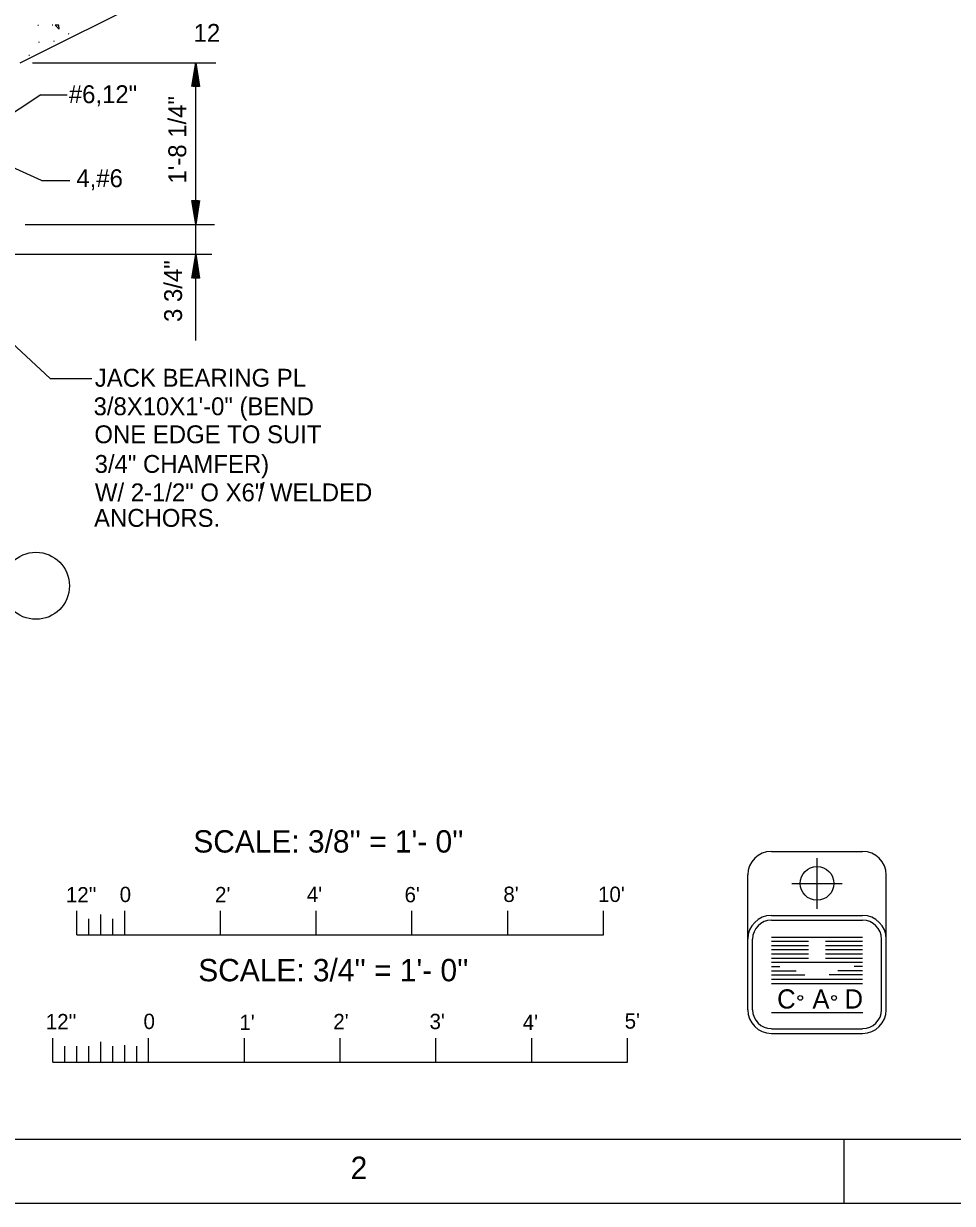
# Model space of a CAD drawing. Extents: x -48 to 108, y -5 to 100.
# Drawn here: x 69.16 to 88.56, y 1.29 to 25.94 of the extents above; entities that cross this region are included whole.
import ezdxf

# ---------------------------------------------------------------- set-up
doc = ezdxf.new("R2010")
doc.units = 0
for name, color, linetype in [('Level 1', 7, 'Continuous'), ('Level 2', 7, 'Continuous'), ('Level 25', 7, 'Continuous'), ('Level 3', 7, 'Continuous'), ('Level 44', 7, 'Continuous'), ('Level 50', 7, 'Continuous')]:
    doc.layers.add(name, color=color, linetype=linetype)

msp = doc.modelspace()

# ---------------------------------------------------------------- linework, layer by layer
at = {"layer": 'Level 1'}
for p, q in [((84.781, 8.644), (86.686, 8.644)), ((85.733, 8.504), (85.733, 7.448)), ((84.288, 5.335), (84.288, 8.152)), ((87.179, 5.335), (87.179, 8.152)), ((85.205, 7.976), (86.261, 7.976)), ((70.275, 6.9), (70.275, 7.4)), ((71.275, 6.9), (71.275, 7.4)), ((73.275, 6.9), (73.275, 7.4)), ((75.275, 6.9), (75.275, 7.4)), ((77.275, 6.9), (77.275, 7.4)), ((79.275, 6.9), (79.275, 7.4)), ((81.275, 6.9), (81.275, 7.4)), ((70.525, 6.9), (70.525, 7.234)), ((70.775, 6.9), (70.775, 7.324)), ((71.025, 6.9), (71.025, 7.234)), ((84.781, 7.307), (86.686, 7.307)), ((84.781, 7.208), (86.686, 7.208)), ((70.275, 6.9), (81.275, 6.9)), ((75.775, 6.9), (75.775, 6.9)), ((84.386, 5.335), (84.386, 6.814)), ((84.781, 6.856), (86.686, 6.856)), ((84.781, 6.768), (85.557, 6.768)), ((84.781, 6.68), (85.557, 6.68)), ((85.909, 6.768), (86.686, 6.768)), ((85.909, 6.68), (86.686, 6.68)), ((87.081, 5.335), (87.081, 6.814)), ((84.781, 6.592), (85.557, 6.592)), ((84.781, 6.504), (85.557, 6.504)), ((84.781, 6.416), (85.557, 6.416)), ((85.909, 6.592), (86.686, 6.592)), ((85.909, 6.504), (86.686, 6.504)), ((85.909, 6.416), (86.686, 6.416)), ((84.781, 6.328), (86.686, 6.328)), ((84.781, 6.24), (84.957, 6.24)), ((86.686, 6.24), (86.51, 6.24)), ((84.781, 6.152), (85.3, 6.152)), ((84.781, 6.064), (85.48, 6.064)), ((84.781, 5.976), (86.686, 5.976)), ((86.686, 6.064), (85.986, 6.064)), ((86.686, 6.152), (86.167, 6.152)), ((84.781, 5.888), (86.686, 5.888)), ((84.781, 5.277), (86.69, 5.277)), ((84.781, 4.941), (86.686, 4.941)), ((69.775, 4.243), (69.775, 4.743)), ((71.775, 4.243), (71.775, 4.743)), ((73.775, 4.243), (73.775, 4.743)), ((75.775, 4.243), (75.775, 4.743)), ((77.775, 4.243), (77.775, 4.743)), ((79.775, 4.243), (79.775, 4.743)), ((81.775, 4.243), (81.775, 4.743)), ((84.781, 4.843), (86.686, 4.843)), ((70.025, 4.243), (70.025, 4.576)), ((70.275, 4.243), (70.275, 4.576)), ((70.525, 4.243), (70.525, 4.576)), ((70.775, 4.243), (70.775, 4.665)), ((71.025, 4.243), (71.025, 4.576)), ((71.275, 4.243), (71.275, 4.595)), ((71.275, 4.243), (71.275, 4.585)), ((71.525, 4.243), (71.525, 4.576)), ((69.775, 4.243), (81.775, 4.243)), ((86.292, 2.625), (86.292, 1.292))]:
    msp.add_line(p, q, dxfattribs=at)
for points in [[(1.292, 75.958), (107.958, 75.958), (107.958, 1.292), (1.292, 1.292)], [(5.292, 74.625), (106.625, 74.625), (106.625, 2.625), (5.292, 2.625)]]:
    msp.add_lwpolyline(points, close=True, dxfattribs=at)
for centre, radius in [((85.734, 7.976), 0.352), ((85.384, 5.583), 0.0493), ((86.09, 5.583), 0.0493)]:
    msp.add_circle(centre, radius, dxfattribs=at)
for centre, radius, start, end in [((84.781, 8.152), 0.493, 90, 180), ((86.686, 8.152), 0.493, 0, 90), ((84.781, 6.814), 0.493, 90, 180), ((84.781, 6.814), 0.394, 90, 180), ((86.686, 6.814), 0.493, 0, 90), ((86.686, 6.814), 0.394, 0, 90), ((84.781, 5.336), 0.493, 180, 270), ((84.781, 5.336), 0.394, 180, 270), ((86.686, 5.336), 0.493, 270, 360), ((86.686, 5.336), 0.394, 270, 360)]:
    msp.add_arc(centre, radius, start, end, dxfattribs=at)
at = {"layer": 'Level 2'}
for p, q in [((69.352, 25.117), (73.181, 25.117)), ((72.758, 21.742), (72.758, 25.117)), ((69.521, 24.446), (68.592, 23.835)), ((69.521, 24.446), (70.071, 24.446)), ((69.534, 22.659), (67.724, 23.48)), ((69.534, 22.659), (70.127, 22.659)), ((69.718, 18.523), (65.925, 22.029)), ((69.195, 21.742), (73.152, 21.742)), ((72.758, 21.117), (72.758, 21.742)), ((66.916, 21.117), (73.094, 21.117)), ((72.758, 19.317), (72.758, 21.117)), ((69.718, 18.523), (70.589, 18.523))]:
    msp.add_line(p, q, dxfattribs=at)
at = {"layer": 'Level 25'}
msp.add_line((69.092, 25.117), (73.673, 27.408), dxfattribs=at)
at = {"layer": 'Level 3'}
msp.add_circle((69.422, 14.192), 0.7, dxfattribs=at)
at = {"layer": 'Level 44'}
for p, q in [((69.477, 25.898), (69.459, 25.898)), ((69.776, 25.904), (69.759, 25.904)), ((70.115, 25.718), (70.098, 25.721)), ((69.491, 25.549), (69.473, 25.544)), ((69.802, 25.567), (69.789, 25.562)), ((69.287, 25.27), (69.273, 25.268))]:
    msp.add_line(p, q, dxfattribs=at)
msp.add_lwpolyline([(69.901, 25.9), (69.821, 25.904), (69.907, 25.816)], close=True, dxfattribs=at)
at = {"layer": 'Level 50'}
for p, q in [((72.758, 25.117), (72.758, 25.117)), ((72.758, 24.979), (72.758, 24.979)), ((72.758, 21.881), (72.758, 21.881)), ((72.758, 21.742), (72.758, 21.742)), ((72.758, 21.117), (72.758, 21.117)), ((72.758, 20.979), (72.758, 20.979))]:
    msp.add_line(p, q, dxfattribs=at)
for points in [[(72.675, 24.619), (72.758, 25.117), (72.84, 24.619), (72.699, 24.619), (72.758, 24.979), (72.814, 24.64), (72.723, 24.64), (72.758, 24.845), (72.787, 24.661), (72.75, 24.661), (72.758, 24.707)], [(72.84, 22.241), (72.758, 21.742), (72.675, 22.241), (72.816, 22.241), (72.758, 21.881), (72.702, 22.22), (72.792, 22.22), (72.758, 22.014), (72.728, 22.198), (72.766, 22.198), (72.758, 22.153)], [(72.675, 20.619), (72.758, 21.117), (72.84, 20.619), (72.699, 20.619), (72.758, 20.979), (72.814, 20.64), (72.723, 20.64), (72.758, 20.845), (72.787, 20.661), (72.75, 20.661), (72.758, 20.707)]]:
    msp.add_lwpolyline(points, dxfattribs=at)

# ---------------------------------------------------------------- texts
at = {"layer": 'Level 1'}
for s, height, p in [("SCALE: 3/8'' = 1'- 0''", 0.46666, (72.709, 8.62)), ("12''", 0.32, (70.047, 7.579)), ('0', 0.32, (71.17, 7.586)), ("2'", 0.32, (73.162, 7.582)), ("4'", 0.32, (75.078, 7.585)), ("6'", 0.32, (77.12, 7.581)), ("8'", 0.32, (79.183, 7.588)), ("10'", 0.32, (81.16, 7.588)), ("SCALE: 3/4'' = 1'- 0''", 0.46666, (72.812, 5.931)), ('C', 0.401, (84.9, 5.362)), ('A', 0.401, (85.637, 5.359)), ('D', 0.401, (86.307, 5.362)), ("12''", 0.32, (69.627, 4.929)), ('0', 0.32, (71.668, 4.934)), ("1'", 0.32, (73.67, 4.911)), ("2'", 0.32, (75.632, 4.931)), ("3'", 0.32, (77.642, 4.932)), ("4'", 0.32, (79.587, 4.912)), ("5'", 0.32, (81.716, 4.942)), ('2', 0.467, (75.994, 1.802))]:
    msp.add_text(s, height=height, dxfattribs=at).set_placement(p)
at = {"layer": 'Level 25'}
for s, height, p in [('12', 0.3733, (72.715, 25.555)), ('#6,12"', 0.3733, (70.108, 24.274)), ('4,#6', 0.3733, (70.265, 22.519)), ('JACK BEARING PL', 0.37333, (70.651, 18.351)), ('3/8X10X1\'-0" (BEND', 0.37333, (70.625, 17.755)), ('ONE EDGE TO SUIT', 0.37333, (70.642, 17.17)), ('3/4" CHAMFER)', 0.37333, (70.647, 16.551)), ('W/ 2-1/2" O X6" WELDED', 0.37333, (70.653, 15.957)), ('/', 0.373, (74.059, 15.965)), ('ANCHORS.', 0.3733, (70.635, 15.424))]:
    msp.add_text(s, height=height, dxfattribs=at).set_placement(p)
for s, p in [('1\'-8 1/4"', (72.56, 22.595)), ('3 3/4"', (72.472, 19.704))]:
    msp.add_text(s, height=0.3733, rotation=90, dxfattribs=at).set_placement(p)

doc.saveas('drawing.dxf')
